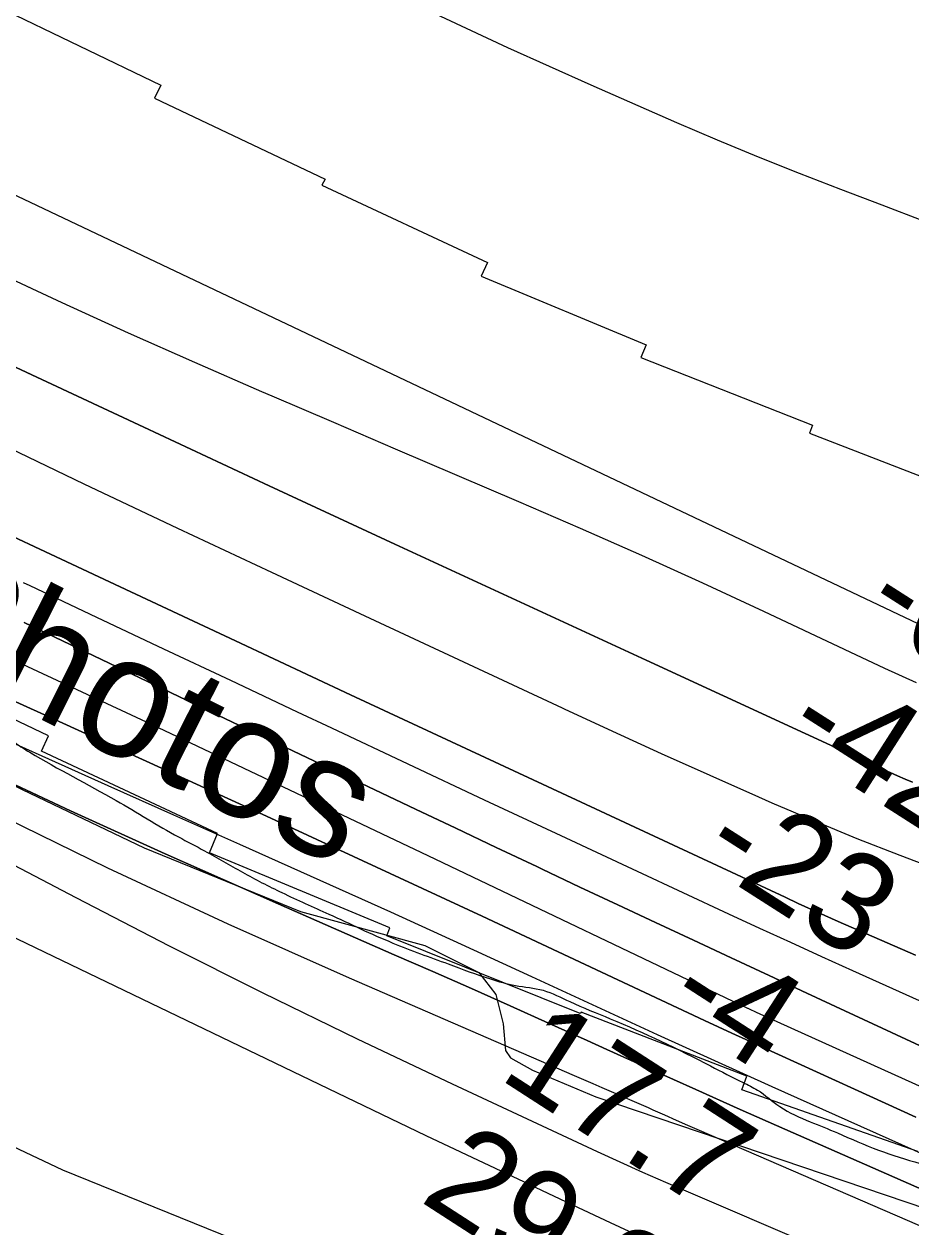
# Model space of a CAD drawing. Extents: x 3297772 to 3335630, y 634068 to 659439.
# Drawn here: x 3318353 to 3318961, y 646514 to 647339 of the extents above; entities that cross this region are included whole.
import ezdxf

# ---------------------------------------------------------------- set-up
doc = ezdxf.new("R2010")
doc.units = 0
for name, color, linetype in [('V-RIVR-EDGE', 7, 'Continuous'), ('V-RIVR-IDEN', 7, 'Continuous'), ('V-RIVR-RANG', 7, 'Continuous'), ('V-RRAP-RVMT', 7, 'Continuous'), ('V-SITE-VEGE', 7, 'Continuous'), ('V-TOPO-DPTH', 7, 'Continuous'), ('V-TOPO-MAJR', 7, 'Continuous'), ('V-TOPO-MINR', 7, 'Continuous'), ('V-TOPO-WATR', 7, 'Continuous')]:
    doc.layers.add(name, color=color, linetype=linetype)

msp = doc.modelspace()

# ---------------------------------------------------------------- linework, layer by layer
at = {"layer": 'V-RIVR-EDGE'}
msp.add_spline([(3314761.96, 649274.13), (3314790.41, 649247.37), (3314813.75, 649224.65), (3314842.19, 649196.8), (3314862.25, 649176.28), (3314886.68, 649152.09), (3314900.17, 649138.17), (3314917.68, 649122.77), (3314932.63, 649107.75), (3314956.32, 649080.27), (3314980.03, 649058.28), (3315004.47, 649036.65), (3315016.5, 649023.47), (3315033.99, 649001.49), (3315053.68, 648981.34), (3315075.92, 648956.42), (3315089.04, 648943.6), (3315090.5, 648939.21), (3315095.23, 648931.52), (3315116.02, 648911.73), (3315165.62, 648868.83), (3315188.61, 648851.6), (3315212.7, 648837.28), (3315236.05, 648818.95), (3315259.03, 648798.78), (3315272.17, 648788.15), (3315288.96, 648777.87), (3315298.45, 648775.29), (3315308.31, 648771.25), (3315320.36, 648764.64), (3315332.04, 648756.2), (3315345.54, 648749.22), (3315365.99, 648738.57), (3315396.29, 648721.68), (3315420.02, 648711.02), (3315449.6, 648697.42), (3315476.26, 648687.12), (3315490.87, 648684.89), (3315496.72, 648684.15), (3315504.02, 648679.38), (3315514.6, 648672.04), (3315516.78, 648666.91), (3315520.77, 648653.38), (3315526.95, 648639.84), (3315536.79, 648627.02), (3315542.99, 648621.52), (3315546.65, 648621.15), (3315552.49, 648618.57), (3315560.15, 648612.71), (3315568.54, 648604.64), (3315578.02, 648595.85), (3315592.98, 648584.84), (3315611.6, 648575.66), (3315624.38, 648570.14), (3315634.97, 648566.83), (3315640.81, 648563.52), (3315648.49, 648562.41), (3315656.17, 648563.12), (3315662.38, 648563.84), (3315671.15, 648560.89), (3315676.25, 648556.12), (3315679.17, 648552.83), (3315684.29, 648552.08), (3315687.94, 648550.98), (3315695.94, 648534.87), (3315725.4, 648474.85), (3315731.95, 648461.31), (3315736.69, 648455.81), (3315746.53, 648446.65), (3315756.75, 648438.22), (3315765.49, 648425.77), (3315772.76, 648408.94), (3315789.52, 648388.06), (3315803.72, 648364.63), (3315814.28, 648346.69), (3315829.95, 648328.37), (3315850.74, 648307.49), (3315869.69, 648285.51), (3315901.78, 648253.62), (3315937.52, 648219.54), (3315960.49, 648195.36), (3315980.91, 648175.57), (3315989.31, 648173.35), (3316000.63, 648165.28), (3316008.65, 648158.32), (3316031.64, 648140.71), (3316054.63, 648124.21), (3316085.29, 648105.49), (3316118.5, 648083.11), (3316140.03, 648068.8), (3316157.19, 648061.81), (3316170.34, 648056.66), (3316187.12, 648044.92), (3316195.52, 648041.24), (3316205.38, 648037.93), (3316215.24, 648033.15), (3316238.61, 648020.67), (3316243.71, 648016.63), (3316255.02, 648007.47), (3316268.9, 648000.12), (3316287.88, 647988.38), (3316303.58, 647982.86), (3316316.73, 647978.44), (3316339.37, 647969.97), (3316356.17, 647962.25), (3316375.52, 647951.24), (3316396.32, 647938.03), (3316428.44, 647920.4), (3316474.07, 647891.41), (3316489.4, 647882.24), (3316507.65, 647873.42), (3316517.51, 647867.91), (3316537.95, 647856.89), (3316563.51, 647842.94), (3316578.83, 647832.3), (3316609.5, 647815.04), (3316632.86, 647802.19), (3316646.72, 647790.82), (3316669.34, 647772.49), (3316682.11, 647762.22), (3316696.35, 647755.24), (3316758.75, 647713.78), (3316797.81, 647691.02), (3316819.71, 647676.71), (3316836.86, 647665.7), (3316864.97, 647650.65), (3316895.64, 647634.12), (3316912.43, 647623.11), (3316940.9, 647606.59), (3316996.75, 647574.65), (3317044.57, 647546.75), (3317079.24, 647525.1), (3317111.36, 647506.38), (3317148.23, 647484.72), (3317188.38, 647460.86), (3317213.92, 647442.15), (3317231.44, 647430.41), (3317255.17, 647416.83), (3317274.14, 647402.16), (3317293.12, 647391.14), (3317310.28, 647384.52), (3317333.65, 647373.5), (3317372.71, 647350.37), (3317404.1, 647330.92), (3317490.98, 647282.82), (3317527.85, 647261.52), (3317547.19, 647249.78), (3317572.38, 647235.83), (3317600.86, 647222.6), (3317628.97, 647207.9), (3317656.71, 647189.92), (3317738.1, 647140.37), (3317755.27, 647133.39), (3317770.25, 647129.33), (3317784.85, 647122.71), (3317816.97, 647104.72), (3317840.71, 647094.79), (3317860.06, 647086.34), (3317887.44, 647070.92), (3317915.19, 647055.49), (3317952.07, 647039.68), (3317972.88, 647031.59), (3318008.3, 647014.32), (3318036.78, 647000.36), (3318074.38, 646981.62), (3318112.35, 646961.06), (3318142.65, 646943.44), (3318179.16, 646929.09), (3318205.1, 646919.89), (3318226.27, 646909.6), (3318257.67, 646892.34), (3318275.56, 646883.53), (3318288.34, 646879.47), (3318295.65, 646878.72), (3318317.19, 646868.8), (3318334.34, 646857.06), (3318347.84, 646845.7), (3318357.33, 646839.46), (3318416.47, 646806.41), (3318459.18, 646781.45), (3318477.06, 646771.9), (3318502.98, 646757.21), (3318530, 646743.26), (3318562.13, 646728.56), (3318605.95, 646708.71), (3318643.93, 646694.36), (3318672.78, 646684.05), (3318689.95, 646679.62), (3318708.95, 646676.28), (3318727.21, 646668.56), (3318754.96, 646656.8), (3318823.61, 646624.46), (3318845.88, 646613.07), (3318855.73, 646607.93), (3318871.06, 646596.56), (3318891.87, 646586.27), (3318910.49, 646578.55), (3318938.61, 646566.78), (3318967.1, 646557.57), (3318997.78, 646547.63), (3319022.25, 646539.16), (3319054.39, 646528.11), (3319074.84, 646519.66), (3319089.46, 646516.33), (3319112.47, 646508.23), (3319131.82, 646500.14), (3319166.88, 646486.53), (3319188.43, 646478.8), (3319196.47, 646478.41), (3319208.52, 646474.73), (3319216.19, 646471.42), (3319227.88, 646467), (3319243.95, 646462.21), (3319256.73, 646456.33), (3319262.2, 646449.74), (3319272.42, 646444.6), (3319289.22, 646438.34), (3319307.11, 646430.25), (3319322.08, 646420.71), (3319337.4, 646408.98), (3319358.2, 646395.03), (3319379.01, 646382.55), (3319389.6, 646379.97), (3319400.56, 646376.29), (3319407.49, 646370.42), (3319419.9, 646362.71), (3319436.33, 646355), (3319463.35, 646343.96), (3319503.52, 646327.78), (3319544.44, 646316.71), (3319579.51, 646307.12), (3319606.17, 646299.38), (3319635.03, 646290.9), (3319681.43, 646280.92), (3319730.75, 646269.46), (3319772.77, 646260.58), (3319801.26, 646254.66), (3319808.94, 646254.65), (3319821.73, 646251.32), (3319836.34, 646248), (3319850.96, 646245.77), (3319868.14, 646245.36), (3319890.79, 646242.38), (3319906.87, 646237.95), (3319922.21, 646232.07), (3319930.98, 646230.95), (3319937.92, 646232.03), (3319943.77, 646231.28), (3319960.57, 646225.03), (3319978.84, 646220.6), (3319994.55, 646217.63), (3320020.12, 646210.62), (3320049.71, 646202.51), (3320078.21, 646196.59), (3320106.71, 646192.13), (3320126.8, 646188.06), (3320144.34, 646184), (3320162.97, 646178.1), (3320179.77, 646173.67), (3320196.59, 646173.27), (3320205.36, 646171.42), (3320223.26, 646166.62), (3320274.75, 646148.95), (3320298.86, 646141.21), (3320341.6, 646127.21), (3320376.3, 646115.8), (3320397.48, 646108.07), (3320422.68, 646098.5), (3320444.95, 646088.58), (3320487.3, 646068.37), (3320513.95, 646053.68), (3320559.94, 646025.78), (3320596.07, 646001.2), (3320629.65, 645979.55), (3320649.72, 645963.78), (3320673.08, 645949.83), (3320682.93, 645941.77), (3320711.02, 645921.23)], degree=3, dxfattribs=at)
at = {"layer": 'V-RRAP-RVMT'}
for p, q in [((3318320.37, 647357.7), (3318447.12, 647296.63)), ((3318447.12, 647296.63), (3318442.83, 647287.81)), ((3318442.83, 647287.81), (3318559.55, 647232.31)), ((3318559.55, 647232.31), (3318557.46, 647228.17)), ((3318557.46, 647228.17), (3318670.83, 647175.16)), ((3318670.83, 647175.16), (3318666.4, 647165.65)), ((3318666.4, 647165.65), (3318779.6, 647118.77)), ((3318779.6, 647118.77), (3318775.93, 647110.01)), ((3318775.93, 647110.01), (3318893.42, 647063.62)), ((3318893.42, 647063.62), (3318891.29, 647058.07)), ((3318891.29, 647058.07), (3319005.93, 647013.76)), ((3318370.22, 646850.6), (3318131.21, 646965.07)), ((3318365.34, 646840.11), (3318370.22, 646850.6)), ((3318485.99, 646783.65), (3318365.34, 646840.11)), ((3318480.54, 646770.4), (3318485.99, 646783.65)), ((3318603.97, 646719.13), (3318480.54, 646770.4)), ((3318601.87, 646713.74), (3318603.97, 646719.13)), ((3318734.33, 646660.31), (3318601.87, 646713.74)), ((3318734.88, 646661.33), (3318734.33, 646660.31)), ((3318848.37, 646617.54), (3318734.88, 646661.33)), ((3318845.07, 646608.06), (3318848.37, 646617.54)), ((3318965.57, 646565.89), (3318845.07, 646608.06))]:
    msp.add_line(p, q, dxfattribs=at)
at = {"layer": 'V-SITE-VEGE'}
for points in [[(3319033.25, 646305.02), (3318778.17, 646400.43), (3318532.62, 646491.06), (3318380.04, 646553.08), (3318122.58, 646674.72), (3317562.35, 646970.49), (3317259.58, 647130.3), (3316840, 647366.43), (3316613.52, 647514.31)], [(3317688.29, 647150.18), (3317818.71, 647081.6), (3317995.96, 646982.91), (3318174.88, 646904.3), (3318352.12, 646813.97), (3318435.73, 646773.83), (3318542.75, 646730.34), (3318628.02, 646706.92), (3318664.81, 646688.52), (3318676.52, 646673.47), (3318681.53, 646653.4), (3318683.2, 646635), (3318686.55, 646629.98), (3318701.6, 646621.61), (3318745.07, 646603.22), (3319169.79, 646459.37)]]:
    msp.add_lwpolyline(points, dxfattribs=at)
at = {"layer": 'V-TOPO-DPTH'}
for points in [[(3318962.03, 646819.02), (3318956.83, 646821.11), (3318951.65, 646823.25), (3318946.52, 646825.49), (3318941.41, 646827.79), (3318779.42, 646902.5), (3318693.36, 646942.26), (3318607.35, 646982.12), (3318521.4, 647022.1), (3318435.48, 647062.17), (3318277.96, 647135.79)], [(3318962.03, 646819.02), (3318956.83, 646821.11), (3318951.65, 646823.25), (3318946.52, 646825.49), (3318941.41, 646827.79), (3318779.42, 646902.5), (3318693.36, 646942.26), (3318607.35, 646982.12), (3318521.4, 647022.1), (3318435.48, 647062.17), (3318277.96, 647135.79)], [(3318330.18, 647054.19), (3318394.28, 647023.44), (3318458.53, 646993.01), (3318522.88, 646962.78), (3318586.76, 646932.97), (3318620.57, 646917.18), (3318654.37, 646901.4), (3318688.18, 646885.6), (3318721.99, 646869.81), (3318723.35, 646869.17), (3318756.53, 646853.81), (3318789.77, 646838.6), (3318823.13, 646823.63), (3318856.55, 646808.82), (3318865.69, 646804.8), (3318894.71, 646792.39), (3318923.88, 646780.35), (3318953.26, 646768.87), (3318982.8, 646757.76)], [(3318330.18, 647054.19), (3318394.28, 647023.44), (3318458.53, 646993.01), (3318522.88, 646962.78), (3318586.76, 646932.97), (3318620.57, 646917.18), (3318654.37, 646901.4), (3318688.18, 646885.6), (3318721.99, 646869.81), (3318723.35, 646869.17), (3318756.53, 646853.81), (3318789.77, 646838.6), (3318823.13, 646823.63), (3318856.55, 646808.82), (3318865.69, 646804.8), (3318894.71, 646792.39), (3318923.88, 646780.35), (3318953.26, 646768.87), (3318982.8, 646757.76)], [(3318290.45, 647013.13), (3318419.36, 646952.71), (3318498.22, 646915.78), (3318577.09, 646878.88), (3318655.99, 646842.02), (3318734.9, 646805.19), (3318874.6, 646740.04), (3318883.68, 646735.84), (3318892.78, 646731.69), (3318901.92, 646727.6), (3318911.07, 646723.55), (3318963.94, 646700.4)], [(3318963.94, 646700.4), (3318911.07, 646723.55), (3318901.92, 646727.6), (3318892.78, 646731.69), (3318883.68, 646735.84), (3318874.6, 646740.04), (3318734.9, 646805.19), (3318655.99, 646842.02), (3318577.09, 646878.88), (3318498.22, 646915.78), (3318419.36, 646952.71), (3318290.45, 647013.13)], [(3319489.68, 646395.42), (3318915.58, 646662.32), (3318889.64, 646674.38), (3318863.71, 646686.45), (3318837.78, 646698.52), (3318811.85, 646710.59), (3318785.94, 646722.7), (3318760.05, 646734.84), (3318734.18, 646747.04), (3318708.32, 646759.27), (3318704.56, 646761.05), (3318676.85, 646774.21), (3318649.13, 646787.37), (3318621.42, 646800.54), (3318593.71, 646813.72), (3318491.28, 646862.44), (3318422.32, 646895.36), (3318353.43, 646928.43)], [(3318353.43, 646928.43), (3318422.32, 646895.36), (3318491.28, 646862.44), (3318593.71, 646813.72), (3318621.42, 646800.54), (3318649.13, 646787.37), (3318676.85, 646774.21), (3318704.56, 646761.05), (3318708.32, 646759.27), (3318734.18, 646747.04), (3318760.05, 646734.84), (3318785.94, 646722.7), (3318811.85, 646710.59), (3318837.78, 646698.52), (3318863.71, 646686.45), (3318889.64, 646674.38), (3318915.58, 646662.32), (3319489.68, 646395.42)], [(3318964.1, 646589.36), (3318922.13, 646608.49), (3318857.12, 646638.22), (3318847.69, 646642.54), (3318838.27, 646646.89), (3318828.86, 646651.26), (3318819.46, 646655.65), (3318667.09, 646727.06), (3318594.86, 646760.73), (3318522.55, 646794.22), (3318450.11, 646827.42), (3318377.58, 646860.42), (3318278.11, 646905.45)], [(3318278.11, 646905.45), (3318377.58, 646860.42), (3318450.11, 646827.42), (3318522.55, 646794.22), (3318594.86, 646760.73), (3318667.09, 646727.06), (3318819.46, 646655.65), (3318828.86, 646651.26), (3318838.27, 646646.89), (3318847.69, 646642.54), (3318857.12, 646638.22), (3318922.13, 646608.49), (3318964.1, 646589.36)], [(3319215.4, 646431.26), (3318874.49, 646581.21), (3318843.95, 646594.72), (3318813.43, 646608.31), (3318782.98, 646622.01), (3318752.55, 646635.8), (3318739.03, 646641.96), (3318712.69, 646653.89), (3318686.32, 646665.73), (3318659.89, 646677.46), (3318633.43, 646689.1), (3318606.94, 646700.7), (3318580.47, 646712.32), (3318554.01, 646723.97), (3318527.56, 646735.65), (3318450.12, 646769.89), (3318385.24, 646799.3), (3318320.75, 646829.51)]]:
    msp.add_lwpolyline(points, dxfattribs=at)
at = {"layer": 'V-TOPO-MAJR'}
for points in [[(3318964.64, 646886.99), (3318943.05, 646896.89), (3318860.06, 646935.93), (3318818.38, 646955.27), (3318776.56, 646974.29), (3318734.54, 646992.86), (3318692.37, 647011.13), (3318650.12, 647029.18), (3318607.87, 647047.24), (3318565.63, 647065.34), (3318523.4, 647083.45), (3318516.18, 647086.55), (3318470.45, 647106.47), (3318424.87, 647126.71), (3318379.5, 647147.43), (3318334.28, 647168.47), (3318249.1, 647208.65), (3318223.68, 647220.77), (3318198.34, 647233.04), (3318173.11, 647245.52), (3318147.94, 647258.15), (3318078.38, 647293.45), (3318018.71, 647324.26), (3317959.33, 647355.62)], [(3317768.16, 647009.16), (3317833.61, 646972.65), (3317932.51, 646917.18), (3317948.42, 646908.23), (3317964.32, 646899.26), (3317980.19, 646890.25), (3317996.06, 646881.21), (3318628.58, 646576.7), (3318652.36, 646565.67), (3318676.08, 646554.49), (3318699.76, 646543.21), (3318703.57, 646541.38), (3318729.16, 646529.2), (3318754.8, 646517.15), (3318780.53, 646505.27), (3318806.31, 646493.52), (3319310.05, 646266.14)]]:
    msp.add_lwpolyline(points, dxfattribs=at)
at = {"layer": 'V-TOPO-MINR'}
for points in [[(3319006.3, 646908.22), (3318254.19, 647265.33), (3318252.09, 647266.08), (3318247.91, 647267.62), (3318243.75, 647269.22), (3318241.69, 647270.08), (3318237.62, 647271.91), (3318231.55, 647274.8), (3318227.25, 647276.88), (3318225.82, 647277.59), (3317832.36, 647473.08), (3317777.07, 647501.04), (3317722.06, 647529.54), (3317667.47, 647558.83), (3317613.16, 647588.65), (3317531.63, 647634.19), (3317518.41, 647641.82), (3317505.33, 647649.69), (3317492.48, 647657.92), (3317479.78, 647666.39), (3317048.21, 648063.91)], [(3317700.66, 647866.31), (3317908.11, 647742.36), (3317984.37, 647697.32), (3318060.93, 647652.8), (3318137.94, 647609.06), (3318215.25, 647565.84), (3318322.3, 647506.7), (3318346.36, 647493.54), (3318370.48, 647480.5), (3318394.71, 647467.66), (3318419, 647454.95), (3318516.23, 647404.55), (3318571.94, 647376.36), (3318628.01, 647348.89), (3318684.59, 647322.53), (3318741.53, 647296.89), (3318800.38, 647271.07), (3318828.25, 647259.11), (3318856.23, 647247.44), (3318884.38, 647236.2), (3318912.66, 647225.26), (3318941.01, 647214.5), (3318969.35, 647203.7)], [(3318277.96, 647135.79), (3318435.48, 647062.17), (3318521.4, 647022.1), (3318607.35, 646982.12), (3318693.36, 646942.26), (3318779.42, 646902.5), (3318941.41, 646827.79), (3318946.52, 646825.49), (3318951.65, 646823.25), (3318956.83, 646821.11), (3318962.03, 646819.02)], [(3318330.18, 647054.19), (3318394.28, 647023.44), (3318458.53, 646993.01), (3318522.88, 646962.78), (3318586.76, 646932.97), (3318620.57, 646917.18), (3318654.37, 646901.4), (3318688.18, 646885.6), (3318721.99, 646869.81), (3318723.35, 646869.17), (3318756.53, 646853.81), (3318789.77, 646838.6), (3318823.13, 646823.63), (3318856.55, 646808.82), (3318865.69, 646804.8), (3318894.71, 646792.39), (3318923.88, 646780.35), (3318953.26, 646768.87), (3318982.8, 646757.76)], [(3318290.45, 647013.13), (3318419.36, 646952.71), (3318498.22, 646915.78), (3318577.09, 646878.88), (3318655.99, 646842.02), (3318734.9, 646805.19), (3318874.6, 646740.04), (3318883.68, 646735.84), (3318892.78, 646731.69), (3318901.92, 646727.6), (3318911.07, 646723.55), (3318963.94, 646700.4)], [(3318352.79, 646955.79), (3318357.3, 646953.66), (3318403.11, 646932.01), (3318448.91, 646910.37), (3318494.73, 646888.75), (3318540.55, 646867.13), (3318563.89, 646856.12), (3318616.23, 646831.49), (3318668.58, 646806.9), (3318720.97, 646782.38), (3318773.38, 646757.91), (3318835.81, 646728.81), (3318857.04, 646718.97), (3318878.31, 646709.18), (3318899.61, 646699.48), (3318920.94, 646689.84), (3319101, 646608.88)], [(3318353.43, 646928.43), (3318422.32, 646895.36), (3318491.28, 646862.44), (3318593.71, 646813.72), (3318621.42, 646800.54), (3318649.13, 646787.37), (3318676.85, 646774.21), (3318704.56, 646761.05), (3318708.32, 646759.27), (3318734.18, 646747.04), (3318760.05, 646734.84), (3318785.94, 646722.7), (3318811.85, 646710.59), (3318837.78, 646698.52), (3318863.71, 646686.45), (3318889.64, 646674.38), (3318915.58, 646662.32), (3319489.68, 646395.42)], [(3318345.43, 646903.11), (3318440.46, 646858.64), (3318535.32, 646813.8), (3318630.07, 646768.73), (3318848.86, 646664.13), (3318849.05, 646664.04), (3318851.08, 646663.09), (3318853.85, 646661.81), (3318854.77, 646661.39), (3319464.76, 646385.47)], [(3318119.88, 646880.85), (3318388.87, 646739.82), (3318452.78, 646706.88), (3318516.99, 646674.54), (3318581.64, 646643.1), (3318646.6, 646612.27), (3318746.04, 646565.91), (3318761.53, 646558.78), (3318777.06, 646551.75), (3318792.65, 646544.87), (3318808.29, 646538.08), (3318891.93, 646502.26)], [(3318320.56, 646857.17), (3318365.62, 646836.92), (3318410.7, 646816.7), (3318455.8, 646796.55), (3318500.93, 646776.44), (3318507.62, 646773.46), (3318556.06, 646751.79), (3318604.44, 646729.98), (3318652.73, 646707.98), (3318700.96, 646685.85), (3318787.07, 646646.12), (3318806.64, 646637.13), (3318826.23, 646628.18), (3318845.85, 646619.3), (3318865.49, 646610.47), (3318997.83, 646551.19)], [(3318320.75, 646829.51), (3318385.24, 646799.3), (3318450.12, 646769.89), (3318527.56, 646735.65), (3318554.01, 646723.97), (3318580.47, 646712.32), (3318606.94, 646700.7), (3318633.43, 646689.1), (3318659.89, 646677.46), (3318686.32, 646665.73), (3318712.69, 646653.89), (3318739.03, 646641.96), (3318752.55, 646635.8), (3318782.98, 646622.01), (3318813.43, 646608.31), (3318843.95, 646594.72), (3318874.49, 646581.21), (3319215.4, 646431.26)], [(3318328.94, 646800.32), (3318410.54, 646760.24), (3318493, 646721.95), (3318576.02, 646684.84), (3318730.28, 646617.91), (3318736.6, 646615.17), (3318742.92, 646612.44), (3318749.25, 646609.71), (3318755.57, 646606.99), (3318761.9, 646604.25), (3318768.21, 646601.49), (3318774.51, 646598.7), (3318780.79, 646595.89), (3318784.09, 646594.4), (3318792.02, 646590.85), (3318799.97, 646587.32), (3318807.93, 646583.82), (3318815.9, 646580.35), (3319426.34, 646316.21)]]:
    msp.add_lwpolyline(points, dxfattribs=at)
at = {"layer": 'V-TOPO-WATR'}
msp.add_lwpolyline([(3318278.11, 646905.45), (3318377.58, 646860.42), (3318450.11, 646827.42), (3318522.55, 646794.22), (3318594.86, 646760.73), (3318667.09, 646727.06), (3318819.46, 646655.65), (3318828.86, 646651.26), (3318838.27, 646646.89), (3318847.69, 646642.54), (3318857.12, 646638.22), (3318922.13, 646608.49), (3318964.1, 646589.36)], dxfattribs=at)

# ---------------------------------------------------------------- texts
at = {"layer": 'V-RIVR-IDEN'}
msp.add_text('Photos', height=83, rotation=333.30045, dxfattribs=at).set_placement((3318259.57, 646914.93))
at = {"layer": 'V-RIVR-RANG'}
for s, rotation, p in [('-63', 327.39964, (3318925.02, 646932.32)), ('-42', 327.39964, (3318871.38, 646847.93)), ('-23', 327.39964, (3318814.18, 646765.8)), ('-4', 327.11833, (3318790.08, 646662.8)), ('17.7', 327.11833, (3318677.52, 646616.49)), ('29.3', 327.11833, (3318623.43, 646532.38))]:
    msp.add_text(s, height=67, rotation=rotation, dxfattribs=at).set_placement(p)

doc.saveas('drawing.dxf')
